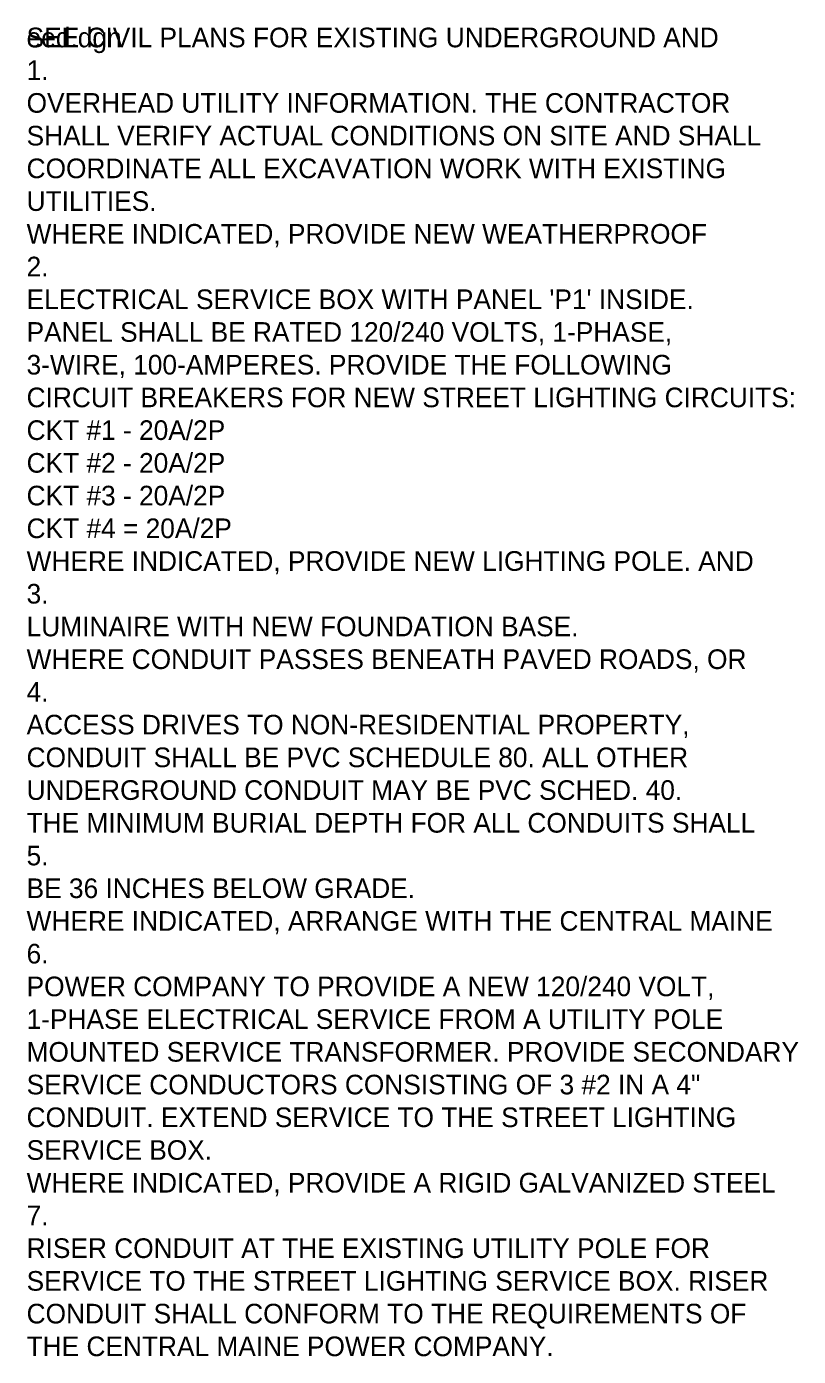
# Model space of a CAD drawing. Extents: x 9916 to 916479, y 6678 to 329942.
# Drawn here: x 9916.3 to 10034.1, y 6678.5 to 6881.7 of the extents above; entities that cross this region are included whole.
import ezdxf

# ---------------------------------------------------------------- set-up
doc = ezdxf.new("R2010")
doc.units = 0
doc.layers.add('H_V CONTROLS', color=7, linetype='Continuous')

msp = doc.modelspace()

# ---------------------------------------------------------------- texts
at = {"layer": 'H_V CONTROLS'}
for s, p in [('eed.dgn', (9916.27, 6878.49)), ('eed.dgn', (9916.27, 6878.49)), ('SEE CIVIL PLANS FOR EXISTING UNDERGROUND AND', (9916.27, 6878.49)), ('SEE CIVIL PLANS FOR EXISTING UNDERGROUND AND', (9916.27, 6878.49)), ('1.', (9916.27, 6873.49)), ('1.', (9916.27, 6873.49)), ('OVERHEAD UTILITY INFORMATION. THE CONTRACTOR', (9916.27, 6868.49)), ('OVERHEAD UTILITY INFORMATION. THE CONTRACTOR', (9916.27, 6868.49)), ('SHALL VERIFY ACTUAL CONDITIONS ON SITE AND SHALL', (9916.27, 6863.49)), ('SHALL VERIFY ACTUAL CONDITIONS ON SITE AND SHALL', (9916.27, 6863.49)), ('COORDINATE ALL EXCAVATION WORK WITH EXISTING', (9916.27, 6858.49)), ('COORDINATE ALL EXCAVATION WORK WITH EXISTING', (9916.27, 6858.49)), ('UTILITIES.', (9916.27, 6853.49)), ('UTILITIES.', (9916.27, 6853.49)), ('WHERE INDICATED, PROVIDE NEW WEATHERPROOF', (9916.27, 6848.49)), ('WHERE INDICATED, PROVIDE NEW WEATHERPROOF', (9916.27, 6848.49)), ('2.', (9916.27, 6843.49)), ('2.', (9916.27, 6843.49)), ("ELECTRICAL SERVICE BOX WITH PANEL 'P1' INSIDE.", (9916.27, 6838.49)), ("ELECTRICAL SERVICE BOX WITH PANEL 'P1' INSIDE.", (9916.27, 6838.49)), ('PANEL SHALL BE RATED 120/240 VOLTS, 1-PHASE,', (9916.27, 6833.49)), ('PANEL SHALL BE RATED 120/240 VOLTS, 1-PHASE,', (9916.27, 6833.49)), ('3-WIRE, 100-AMPERES. PROVIDE THE FOLLOWING', (9916.27, 6828.49)), ('3-WIRE, 100-AMPERES. PROVIDE THE FOLLOWING', (9916.27, 6828.49)), ('CIRCUIT BREAKERS FOR NEW STREET LIGHTING CIRCUITS:', (9916.27, 6823.49)), ('CIRCUIT BREAKERS FOR NEW STREET LIGHTING CIRCUITS:', (9916.27, 6823.49)), ('CKT #1 - 20A/2P', (9916.27, 6818.49)), ('CKT #1 - 20A/2P', (9916.27, 6818.49)), ('CKT #2 - 20A/2P', (9916.27, 6813.49)), ('CKT #2 - 20A/2P', (9916.27, 6813.49)), ('CKT #3 - 20A/2P', (9916.27, 6808.49)), ('CKT #3 - 20A/2P', (9916.27, 6808.49)), ('CKT #4 = 20A/2P', (9916.27, 6803.49)), ('CKT #4 = 20A/2P', (9916.27, 6803.49)), ('WHERE INDICATED, PROVIDE NEW LIGHTING POLE. AND', (9916.27, 6798.49)), ('WHERE INDICATED, PROVIDE NEW LIGHTING POLE. AND', (9916.27, 6798.49)), ('3.', (9916.27, 6793.49)), ('3.', (9916.27, 6793.49)), ('LUMINAIRE WITH NEW FOUNDATION BASE.', (9916.27, 6788.49)), ('LUMINAIRE WITH NEW FOUNDATION BASE.', (9916.27, 6788.49)), ('WHERE CONDUIT PASSES BENEATH PAVED ROADS, OR', (9916.27, 6783.49)), ('WHERE CONDUIT PASSES BENEATH PAVED ROADS, OR', (9916.27, 6783.49)), ('4.', (9916.27, 6778.49)), ('4.', (9916.27, 6778.49)), ('ACCESS DRIVES TO NON-RESIDENTIAL PROPERTY,', (9916.27, 6773.49)), ('ACCESS DRIVES TO NON-RESIDENTIAL PROPERTY,', (9916.27, 6773.49)), ('CONDUIT SHALL BE PVC SCHEDULE 80. ALL OTHER', (9916.27, 6768.49)), ('CONDUIT SHALL BE PVC SCHEDULE 80. ALL OTHER', (9916.27, 6768.49)), ('UNDERGROUND CONDUIT MAY BE PVC SCHED. 40.', (9916.27, 6763.49)), ('UNDERGROUND CONDUIT MAY BE PVC SCHED. 40.', (9916.27, 6763.49)), ('THE MINIMUM BURIAL DEPTH FOR ALL CONDUITS SHALL', (9916.27, 6758.49)), ('THE MINIMUM BURIAL DEPTH FOR ALL CONDUITS SHALL', (9916.27, 6758.49)), ('5.', (9916.27, 6753.49)), ('5.', (9916.27, 6753.49)), ('BE 36 INCHES BELOW GRADE.', (9916.27, 6748.49)), ('BE 36 INCHES BELOW GRADE.', (9916.27, 6748.49)), ('WHERE INDICATED, ARRANGE WITH THE CENTRAL MAINE', (9916.27, 6743.49)), ('WHERE INDICATED, ARRANGE WITH THE CENTRAL MAINE', (9916.27, 6743.49)), ('6.', (9916.27, 6738.49)), ('6.', (9916.27, 6738.49)), ('POWER COMPANY TO PROVIDE A NEW 120/240 VOLT,', (9916.27, 6733.49)), ('POWER COMPANY TO PROVIDE A NEW 120/240 VOLT,', (9916.27, 6733.49)), ('1-PHASE ELECTRICAL SERVICE FROM A UTILITY POLE', (9916.27, 6728.49)), ('1-PHASE ELECTRICAL SERVICE FROM A UTILITY POLE', (9916.27, 6728.49)), ('MOUNTED SERVICE TRANSFORMER. PROVIDE SECONDARY', (9916.27, 6723.49)), ('MOUNTED SERVICE TRANSFORMER. PROVIDE SECONDARY', (9916.27, 6723.49)), ('SERVICE CONDUCTORS CONSISTING OF 3 #2 IN A 4"', (9916.27, 6718.49)), ('SERVICE CONDUCTORS CONSISTING OF 3 #2 IN A 4"', (9916.27, 6718.49)), ('CONDUIT. EXTEND SERVICE TO THE STREET LIGHTING', (9916.27, 6713.49)), ('CONDUIT. EXTEND SERVICE TO THE STREET LIGHTING', (9916.27, 6713.49)), ('SERVICE BOX.', (9916.27, 6708.49)), ('SERVICE BOX.', (9916.27, 6708.49)), ('WHERE INDICATED, PROVIDE A RIGID GALVANIZED STEEL', (9916.27, 6703.49)), ('WHERE INDICATED, PROVIDE A RIGID GALVANIZED STEEL', (9916.27, 6703.49)), ('7.', (9916.27, 6698.49)), ('7.', (9916.27, 6698.49)), ('RISER CONDUIT AT THE EXISTING UTILITY POLE FOR', (9916.27, 6693.49)), ('RISER CONDUIT AT THE EXISTING UTILITY POLE FOR', (9916.27, 6693.49)), ('SERVICE TO THE STREET LIGHTING SERVICE BOX. RISER', (9916.27, 6688.49)), ('SERVICE TO THE STREET LIGHTING SERVICE BOX. RISER', (9916.27, 6688.49)), ('CONDUIT SHALL CONFORM TO THE REQUIREMENTS OF', (9916.27, 6683.49)), ('CONDUIT SHALL CONFORM TO THE REQUIREMENTS OF', (9916.27, 6683.49)), ('THE CENTRAL MAINE POWER COMPANY.', (9916.27, 6678.49)), ('THE CENTRAL MAINE POWER COMPANY.', (9916.27, 6678.49))]:
    msp.add_text(s, height=3, dxfattribs=at).set_placement(p)

doc.saveas('drawing.dxf')
